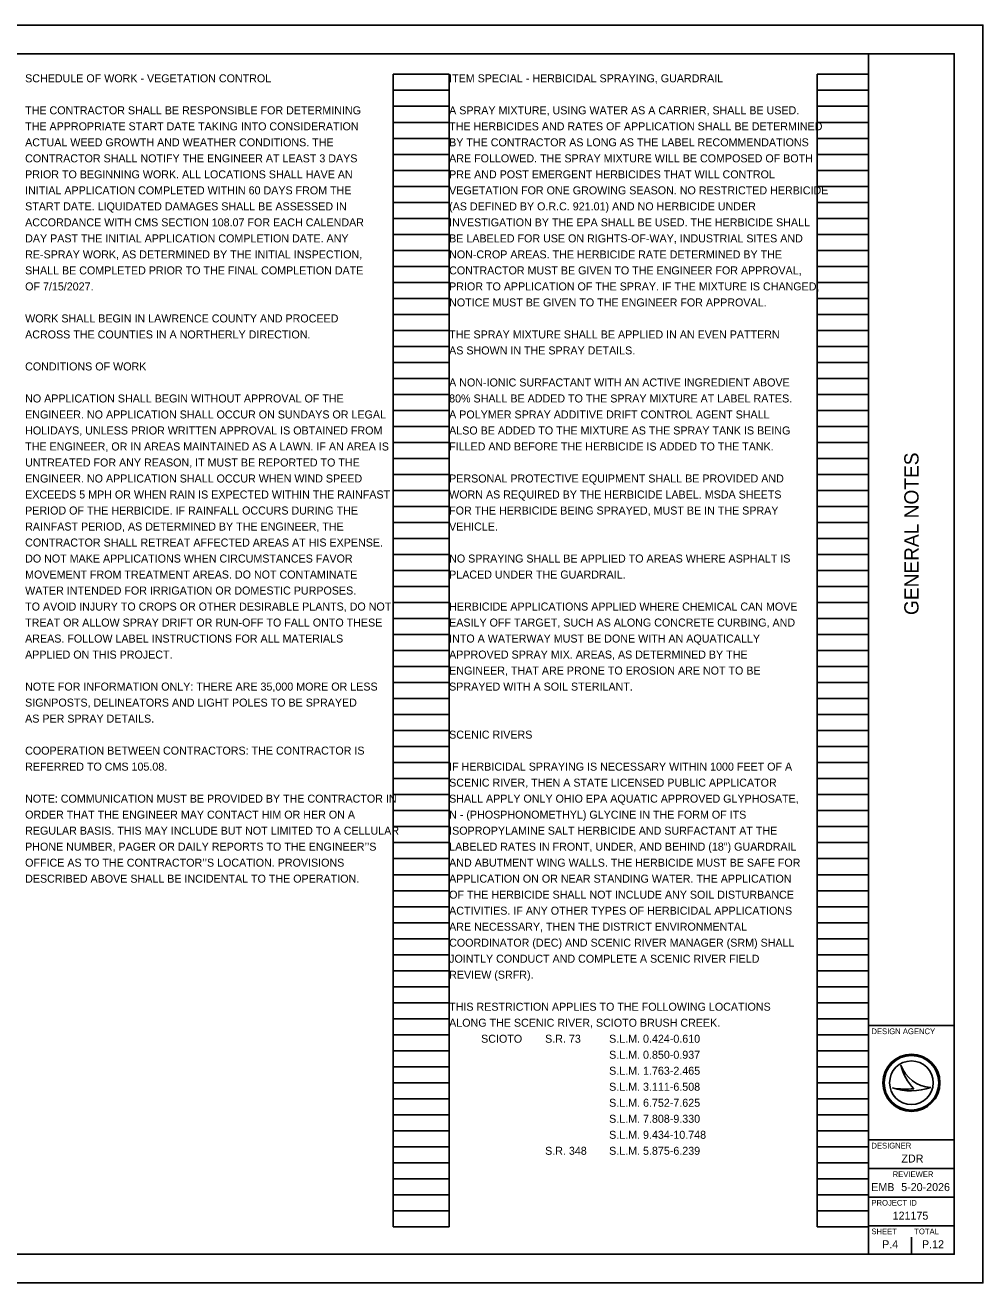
# Model space of a CAD drawing. Extents: x 0 to 34, y 0 to 22.
# Drawn here: x 17.24 to 34, y 0 to 22 of the extents above; entities that cross this region are included whole.
import ezdxf

# ---------------------------------------------------------------- set-up
doc = ezdxf.new("R2010")
doc.units = 0
for name, color, linetype in [('SH_Border', 7, 'Continuous'), ('SH_Cut_Line', 7, 'Continuous'), ('SH_Data', 7, 'Continuous'), ('SH_Text', 7, 'Continuous')]:
    doc.layers.add(name, color=color, linetype=linetype)

msp = doc.modelspace()

# ---------------------------------------------------------------- linework, layer by layer
at = {"layer": 'SH_Border'}
for p, q in [((32, 0.5), (32, 21.5)), ((32, 4.5), (33.5, 4.5)), ((32, 2.5), (33.5, 2.5)), ((32, 2), (33.5, 2)), ((32, 1.5), (33.5, 1.5)), ((32, 1), (33.5, 1))]:
    msp.add_line(p, q, dxfattribs=at)
msp.add_lwpolyline([(1.5, 21.5), (33.5, 21.5), (33.5, 0.5), (1.5, 0.5)], close=True, dxfattribs=at)
at = {"layer": 'SH_Cut_Line'}
msp.add_lwpolyline([(0, 0), (34, 0), (34, 22), (0, 22)], close=True, dxfattribs=at)
at = {"layer": 'SH_Data'}
for p, q in [((23.68, 0.98), (23.68, 21.14)), ((23.68, 21.14), (24.66, 21.14)), ((24.66, 0.98), (24.66, 21.14)), ((31.1, 0.98), (31.1, 21.14)), ((31.1, 21.14), (32, 21.14)), ((32, 0.98), (32, 21.14)), ((23.68, 20.86), (24.66, 20.86)), ((31.1, 20.86), (32, 20.86)), ((23.68, 20.58), (24.66, 20.58)), ((31.1, 20.58), (32, 20.58)), ((23.68, 20.3), (24.66, 20.3)), ((31.1, 20.3), (32, 20.3)), ((23.68, 20.02), (24.66, 20.02)), ((31.1, 20.02), (32, 20.02)), ((23.68, 19.74), (24.66, 19.74)), ((31.1, 19.74), (32, 19.74)), ((23.68, 19.46), (24.66, 19.46)), ((31.1, 19.46), (32, 19.46)), ((23.68, 19.18), (24.66, 19.18)), ((31.1, 19.18), (32, 19.18)), ((23.68, 18.9), (24.66, 18.9)), ((31.1, 18.9), (32, 18.9)), ((23.68, 18.62), (24.66, 18.62)), ((31.1, 18.62), (32, 18.62)), ((23.68, 18.34), (24.66, 18.34)), ((31.1, 18.34), (32, 18.34)), ((23.68, 18.06), (24.66, 18.06)), ((31.1, 18.06), (32, 18.06)), ((23.68, 17.78), (24.66, 17.78)), ((31.1, 17.78), (32, 17.78)), ((23.68, 17.5), (24.66, 17.5)), ((31.1, 17.5), (32, 17.5)), ((23.68, 17.22), (24.66, 17.22)), ((31.1, 17.22), (32, 17.22)), ((23.68, 16.94), (24.66, 16.94)), ((31.1, 16.94), (32, 16.94)), ((23.68, 16.66), (24.66, 16.66)), ((31.1, 16.66), (32, 16.66)), ((23.68, 16.38), (24.66, 16.38)), ((31.1, 16.38), (32, 16.38)), ((23.68, 16.1), (24.66, 16.1)), ((31.1, 16.1), (32, 16.1)), ((23.68, 15.82), (24.66, 15.82)), ((31.1, 15.82), (32, 15.82)), ((23.68, 15.54), (24.66, 15.54)), ((31.1, 15.54), (32, 15.54)), ((23.68, 15.26), (24.66, 15.26)), ((31.1, 15.26), (32, 15.26)), ((23.68, 14.98), (24.66, 14.98)), ((31.1, 14.98), (32, 14.98)), ((23.68, 14.7), (24.66, 14.7)), ((31.1, 14.7), (32, 14.7)), ((23.68, 14.42), (24.66, 14.42)), ((31.1, 14.42), (32, 14.42)), ((23.68, 14.14), (24.66, 14.14)), ((31.1, 14.14), (32, 14.14)), ((23.68, 13.86), (24.66, 13.86)), ((31.1, 13.86), (32, 13.86)), ((23.68, 13.58), (24.66, 13.58)), ((31.1, 13.58), (32, 13.58)), ((23.68, 13.3), (24.66, 13.3)), ((31.1, 13.3), (32, 13.3)), ((23.68, 13.02), (24.66, 13.02)), ((31.1, 13.02), (32, 13.02)), ((23.68, 12.74), (24.66, 12.74)), ((31.1, 12.74), (32, 12.74)), ((23.68, 12.46), (24.66, 12.46)), ((31.1, 12.46), (32, 12.46)), ((23.68, 12.18), (24.66, 12.18)), ((31.1, 12.18), (32, 12.18)), ((23.68, 11.9), (24.66, 11.9)), ((31.1, 11.9), (32, 11.9)), ((23.68, 11.62), (24.66, 11.62)), ((31.1, 11.62), (32, 11.62)), ((23.68, 11.34), (24.66, 11.34)), ((31.1, 11.34), (32, 11.34)), ((23.68, 11.06), (24.66, 11.06)), ((31.1, 11.06), (32, 11.06)), ((23.68, 10.78), (24.66, 10.78)), ((31.1, 10.78), (32, 10.78)), ((23.68, 10.5), (24.66, 10.5)), ((31.1, 10.5), (32, 10.5)), ((23.68, 10.22), (24.66, 10.22)), ((31.1, 10.22), (32, 10.22)), ((23.68, 9.94), (24.66, 9.94)), ((31.1, 9.94), (32, 9.94)), ((23.68, 9.66), (24.66, 9.66)), ((31.1, 9.66), (32, 9.66)), ((23.68, 9.38), (24.66, 9.38)), ((31.1, 9.38), (32, 9.38)), ((23.68, 9.1), (24.66, 9.1)), ((31.1, 9.1), (32, 9.1)), ((23.68, 8.82), (24.66, 8.82)), ((31.1, 8.82), (32, 8.82)), ((23.68, 8.54), (24.66, 8.54)), ((31.1, 8.54), (32, 8.54)), ((23.68, 8.26), (24.66, 8.26)), ((31.1, 8.26), (32, 8.26)), ((23.68, 7.98), (24.66, 7.98)), ((31.1, 7.98), (32, 7.98)), ((23.68, 7.7), (24.66, 7.7)), ((31.1, 7.7), (32, 7.7)), ((23.68, 7.42), (24.66, 7.42)), ((31.1, 7.42), (32, 7.42)), ((23.68, 7.14), (24.66, 7.14)), ((31.1, 7.14), (32, 7.14)), ((23.68, 6.86), (24.66, 6.86)), ((31.1, 6.86), (32, 6.86)), ((23.68, 6.58), (24.66, 6.58)), ((31.1, 6.58), (32, 6.58)), ((23.68, 6.3), (24.66, 6.3)), ((31.1, 6.3), (32, 6.3)), ((23.68, 6.02), (24.66, 6.02)), ((31.1, 6.02), (32, 6.02)), ((23.68, 5.74), (24.66, 5.74)), ((31.1, 5.74), (32, 5.74)), ((23.68, 5.46), (24.66, 5.46)), ((31.1, 5.46), (32, 5.46)), ((23.68, 5.18), (24.66, 5.18)), ((31.1, 5.18), (32, 5.18)), ((23.68, 4.9), (24.66, 4.9)), ((31.1, 4.9), (32, 4.9)), ((23.68, 4.62), (24.66, 4.62)), ((31.1, 4.62), (32, 4.62)), ((23.68, 4.34), (24.66, 4.34)), ((31.1, 4.34), (32, 4.34)), ((23.68, 4.06), (24.66, 4.06)), ((31.1, 4.06), (32, 4.06)), ((23.68, 3.78), (24.66, 3.78)), ((31.1, 3.78), (32, 3.78)), ((32.567, 3.81), (32.567, 3.81)), ((23.68, 3.5), (24.66, 3.5)), ((31.1, 3.5), (32, 3.5)), ((32.417, 3.41), (32.417, 3.41)), ((32.75, 3.5), (32.75, 3.5)), ((33.087, 3.419), (33.087, 3.419)), ((23.68, 3.22), (24.66, 3.22)), ((31.1, 3.22), (32, 3.22)), ((23.68, 2.94), (24.66, 2.94)), ((31.1, 2.94), (32, 2.94)), ((23.68, 2.66), (24.66, 2.66)), ((31.1, 2.66), (32, 2.66)), ((23.68, 2.38), (24.66, 2.38)), ((31.1, 2.38), (32, 2.38)), ((23.68, 2.1), (24.66, 2.1)), ((31.1, 2.1), (32, 2.1)), ((23.68, 1.82), (24.66, 1.82)), ((31.1, 1.82), (32, 1.82)), ((23.68, 1.54), (24.66, 1.54)), ((31.1, 1.54), (32, 1.54)), ((23.68, 1.26), (24.66, 1.26)), ((31.1, 1.26), (32, 1.26)), ((23.68, 0.98), (24.66, 0.98)), ((31.1, 0.98), (32, 0.98)), ((32.375, 0.675), (32.375, 0.675)), ((32.75, 0.5), (32.75, 0.8))]:
    msp.add_line(p, q, dxfattribs=at)
for radius in [0.5, 0.477, 0.477, 0.382]:
    msp.add_circle((32.75, 3.5), radius, dxfattribs=at)
for centre, radius, start, end in [((33.116, 3.998), 0.58, 198.9257, 198.9319), ((33.347, 3.97), 0.796, 191.6379, 191.6421), ((33.116, 3.998), 0.58, 198.9319, 267.1657), ((33.347, 3.97), 0.796, 191.6421, 226.0947), ((32.739, 4.37), 1.013, 251.4576, 290.0832), ((32.648, 4.654), 1.266, 259.4964, 259.4995), ((32.739, 4.37), 1.013, 251.4527, 251.4576), ((32.648, 4.654), 1.266, 259.4995, 276.6672)]:
    msp.add_arc(centre, radius, start, end, dxfattribs=at)

# ---------------------------------------------------------------- texts
msp.add_text('GENERAL NOTES', height=0.25, rotation=90, dxfattribs=at).set_placement((32.875, 11.682))
for s, height, p in [('DESIGN AGENCY', 0.1, (32.05, 4.35)), ('DESIGNER', 0.1, (32.05, 2.35)), ('ZDR', 0.14, (32.575, 2.105)), ('REVIEWER', 0.1, (32.422, 1.85)), ('EMB', 0.14, (32.047, 1.605)), ('5-20-2026', 0.14, (32.571, 1.605)), ('PROJECT ID', 0.1, (32.05, 1.35)), ('121175', 0.14, (32.421, 1.105)), ('SHEET', 0.1, (32.05, 0.85)), ('TOTAL', 0.1, (32.8, 0.85)), ('P.4', 0.14, (32.237, 0.605)), ('P.12', 0.14, (32.935, 0.605))]:
    msp.add_text(s, height=height, dxfattribs=at).set_placement(p)
at = {"layer": 'SH_Text'}
for s, p in [('SCHEDULE OF WORK - VEGETATION CONTROL', (17.24, 21)), ('ITEM SPECIAL - HERBICIDAL SPRAYING, GUARDRAIL', (24.66, 21)), ('THE CONTRACTOR SHALL BE RESPONSIBLE FOR DETERMINING ', (17.24, 20.44)), ('A SPRAY MIXTURE, USING WATER AS A CARRIER, SHALL BE USED.', (24.66, 20.44)), ('THE APPROPRIATE START DATE TAKING INTO CONSIDERATION', (17.24, 20.16)), ('THE HERBICIDES AND RATES OF APPLICATION SHALL BE DETERMINED ', (24.66, 20.16)), ('ACTUAL WEED GROWTH AND WEATHER CONDITIONS. THE ', (17.24, 19.88)), ('BY THE CONTRACTOR AS LONG AS THE LABEL RECOMMENDATIONS', (24.66, 19.88)), ('CONTRACTOR SHALL NOTIFY THE ENGINEER AT LEAST 3 DAYS', (17.24, 19.6)), ('ARE FOLLOWED. THE SPRAY MIXTURE WILL BE COMPOSED OF BOTH', (24.66, 19.6)), ('PRIOR TO BEGINNING WORK. ALL LOCATIONS SHALL HAVE AN ', (17.24, 19.32)), ('PRE AND POST EMERGENT HERBICIDES THAT WILL CONTROL', (24.66, 19.32)), ('INITIAL APPLICATION COMPLETED WITHIN 60 DAYS FROM THE ', (17.24, 19.04)), ('VEGETATION FOR ONE GROWING SEASON. NO RESTRICTED HERBICIDE', (24.66, 19.04)), ('START DATE. LIQUIDATED DAMAGES SHALL BE ASSESSED IN', (17.24, 18.76)), ('(AS DEFINED BY O.R.C. 921.01) AND NO HERBICIDE UNDER', (24.66, 18.76)), ('ACCORDANCE WITH CMS SECTION 108.07 FOR EACH CALENDAR ', (17.24, 18.48)), ('INVESTIGATION BY THE EPA SHALL BE USED. THE HERBICIDE SHALL', (24.66, 18.48)), ('DAY PAST THE INITIAL APPLICATION COMPLETION DATE. ANY ', (17.24, 18.2)), ('BE LABELED FOR USE ON RIGHTS-OF-WAY, INDUSTRIAL SITES AND', (24.66, 18.2)), ('RE-SPRAY WORK, AS DETERMINED BY THE INITIAL INSPECTION,', (17.24, 17.92)), ('NON-CROP AREAS. THE HERBICIDE RATE DETERMINED BY THE', (24.66, 17.92)), ('SHALL BE COMPLETED PRIOR TO THE FINAL COMPLETION DATE', (17.24, 17.64)), ('CONTRACTOR MUST BE GIVEN TO THE ENGINEER FOR APPROVAL,', (24.66, 17.64)), ('OF 7/15/2027.', (17.24, 17.36)), ('PRIOR TO APPLICATION OF THE SPRAY. IF THE MIXTURE IS CHANGED,', (24.66, 17.36)), ('NOTICE MUST BE GIVEN TO THE ENGINEER FOR APPROVAL.', (24.66, 17.08)), ('WORK SHALL BEGIN IN LAWRENCE COUNTY AND PROCEED', (17.24, 16.8)), ('ACROSS THE COUNTIES IN A NORTHERLY DIRECTION.', (17.24, 16.52)), ('THE SPRAY MIXTURE SHALL BE APPLIED IN AN EVEN PATTERN', (24.66, 16.52)), ('AS SHOWN IN THE SPRAY DETAILS.', (24.66, 16.24)), ('CONDITIONS OF WORK', (17.24, 15.96)), ('A NON-IONIC SURFACTANT WITH AN ACTIVE INGREDIENT ABOVE', (24.66, 15.68)), ('NO APPLICATION SHALL BEGIN WITHOUT APPROVAL OF THE', (17.24, 15.4)), ('80% SHALL BE ADDED TO THE SPRAY MIXTURE AT LABEL RATES.', (24.66, 15.4)), ('ENGINEER. NO APPLICATION SHALL OCCUR ON SUNDAYS OR LEGAL', (17.24, 15.12)), ('A POLYMER SPRAY ADDITIVE DRIFT CONTROL AGENT SHALL', (24.66, 15.12)), ('HOLIDAYS, UNLESS PRIOR WRITTEN APPROVAL IS OBTAINED FROM', (17.24, 14.84)), ('ALSO BE ADDED TO THE MIXTURE AS THE SPRAY TANK IS BEING', (24.66, 14.84)), ('THE ENGINEER, OR IN AREAS MAINTAINED AS A LAWN. IF AN AREA IS ', (17.24, 14.56)), ('FILLED AND BEFORE THE HERBICIDE IS ADDED TO THE TANK.', (24.66, 14.56)), ('UNTREATED FOR ANY REASON, IT MUST BE REPORTED TO THE', (17.24, 14.28)), ('ENGINEER. NO APPLICATION SHALL OCCUR WHEN WIND SPEED', (17.24, 14)), ('PERSONAL PROTECTIVE EQUIPMENT SHALL BE PROVIDED AND', (24.66, 14)), ('EXCEEDS 5 MPH OR WHEN RAIN IS EXPECTED WITHIN THE RAINFAST', (17.24, 13.72)), ('WORN AS REQUIRED BY THE HERBICIDE LABEL. MSDA SHEETS', (24.66, 13.72)), ('PERIOD OF THE HERBICIDE. IF RAINFALL OCCURS DURING THE', (17.24, 13.44)), ('FOR THE HERBICIDE BEING SPRAYED, MUST BE IN THE SPRAY', (24.66, 13.44)), ('RAINFAST PERIOD, AS DETERMINED BY THE ENGINEER, THE ', (17.24, 13.16)), ('VEHICLE.', (24.66, 13.16)), ('CONTRACTOR SHALL RETREAT AFFECTED AREAS AT HIS EXPENSE.', (17.24, 12.88)), ('DO NOT MAKE APPLICATIONS WHEN CIRCUMSTANCES FAVOR', (17.24, 12.6)), ('NO SPRAYING SHALL BE APPLIED TO AREAS WHERE ASPHALT IS', (24.66, 12.6)), ('MOVEMENT FROM TREATMENT AREAS. DO NOT CONTAMINATE', (17.24, 12.32)), ('PLACED UNDER THE GUARDRAIL.', (24.66, 12.32)), ('WATER INTENDED FOR IRRIGATION OR DOMESTIC PURPOSES.', (17.24, 12.04)), ('TO AVOID INJURY TO CROPS OR OTHER DESIRABLE PLANTS, DO NOT', (17.24, 11.76)), ('HERBICIDE APPLICATIONS APPLIED WHERE CHEMICAL CAN MOVE', (24.66, 11.76)), ('TREAT OR ALLOW SPRAY DRIFT OR RUN-OFF TO FALL ONTO THESE', (17.24, 11.48)), ('EASILY OFF TARGET, SUCH AS ALONG CONCRETE CURBING, AND', (24.66, 11.48)), ('AREAS. FOLLOW LABEL INSTRUCTIONS FOR ALL MATERIALS', (17.24, 11.2)), ('INTO A WATERWAY MUST BE DONE WITH AN AQUATICALLY', (24.66, 11.2)), ('APPLIED ON THIS PROJECT.', (17.24, 10.92)), ('APPROVED SPRAY MIX. AREAS, AS DETERMINED BY THE ', (24.66, 10.92)), ('ENGINEER, THAT ARE PRONE TO EROSION ARE NOT TO BE ', (24.66, 10.64)), ('NOTE FOR INFORMATION ONLY: THERE ARE 35,000 MORE OR LESS', (17.24, 10.36)), ('SPRAYED WITH A SOIL STERILANT.', (24.66, 10.36)), ('SIGNPOSTS, DELINEATORS AND LIGHT POLES TO BE SPRAYED', (17.24, 10.08)), ('AS PER SPRAY DETAILS.', (17.24, 9.8)), ('SCENIC RIVERS', (24.66, 9.52)), ('COOPERATION BETWEEN CONTRACTORS: THE CONTRACTOR IS', (17.24, 9.24)), ('REFERRED TO CMS 105.08.', (17.24, 8.96)), ('IF HERBICIDAL SPRAYING IS NECESSARY WITHIN 1000 FEET OF A ', (24.66, 8.96)), ('SCENIC RIVER, THEN A STATE LICENSED PUBLIC APPLICATOR ', (24.66, 8.68)), ('NOTE: COMMUNICATION MUST BE PROVIDED BY THE CONTRACTOR IN', (17.24, 8.4)), ('SHALL APPLY ONLY OHIO EPA AQUATIC APPROVED GLYPHOSATE,', (24.66, 8.4)), ('ORDER THAT THE ENGINEER MAY CONTACT HIM OR HER ON A ', (17.24, 8.12)), ('N - (PHOSPHONOMETHYL) GLYCINE IN THE FORM OF ITS', (24.66, 8.12)), ('REGULAR BASIS. THIS MAY INCLUDE BUT NOT LIMITED TO A CELLULAR', (17.24, 7.84)), ('ISOPROPYLAMINE SALT HERBICIDE AND SURFACTANT AT THE', (24.66, 7.84)), ('PHONE NUMBER, PAGER OR DAILY REPORTS TO THE ENGINEER’’S ', (17.24, 7.56)), ('LABELED RATES IN FRONT, UNDER, AND BEHIND (18") GUARDRAIL', (24.66, 7.56)), ('OFFICE AS TO THE CONTRACTOR’’S LOCATION. PROVISIONS', (17.24, 7.28)), ('AND ABUTMENT WING WALLS. THE HERBICIDE MUST BE SAFE FOR ', (24.66, 7.28)), ('DESCRIBED ABOVE SHALL BE INCIDENTAL TO THE OPERATION.', (17.24, 7)), ('APPLICATION ON OR NEAR STANDING WATER. THE APPLICATION ', (24.66, 7)), ('OF THE HERBICIDE SHALL NOT INCLUDE ANY SOIL DISTURBANCE', (24.66, 6.72)), ('ACTIVITIES. IF ANY OTHER TYPES OF HERBICIDAL APPLICATIONS', (24.66, 6.44)), ('ARE NECESSARY, THEN THE DISTRICT ENVIRONMENTAL ', (24.66, 6.16)), ('COORDINATOR (DEC) AND SCENIC RIVER MANAGER (SRM) SHALL ', (24.66, 5.88)), ('JOINTLY CONDUCT AND COMPLETE A SCENIC RIVER FIELD ', (24.66, 5.6)), ('REVIEW (SRFR).', (24.66, 5.32)), ('THIS RESTRICTION APPLIES TO THE FOLLOWING LOCATIONS', (24.66, 4.76)), ('ALONG THE SCENIC RIVER, SCIOTO BRUSH CREEK.', (24.66, 4.48)), ('SCIOTO ', (25.22, 4.2)), ('S.R. 73 ', (26.34, 4.2)), ('S.L.M. 0.424-0.610', (27.46, 4.2)), ('S.L.M. 0.850-0.937', (27.46, 3.92)), ('S.L.M. 1.763-2.465', (27.46, 3.64)), ('S.L.M. 3.111-6.508', (27.46, 3.36)), ('S.L.M. 6.752-7.625', (27.46, 3.08)), ('S.L.M. 7.808-9.330', (27.46, 2.8)), ('S.L.M. 9.434-10.748', (27.46, 2.52)), ('S.R. 348', (26.34, 2.24)), ('S.L.M. 5.875-6.239', (27.46, 2.24))]:
    msp.add_text(s, height=0.14, dxfattribs=at).set_placement(p)

doc.saveas('drawing.dxf')
